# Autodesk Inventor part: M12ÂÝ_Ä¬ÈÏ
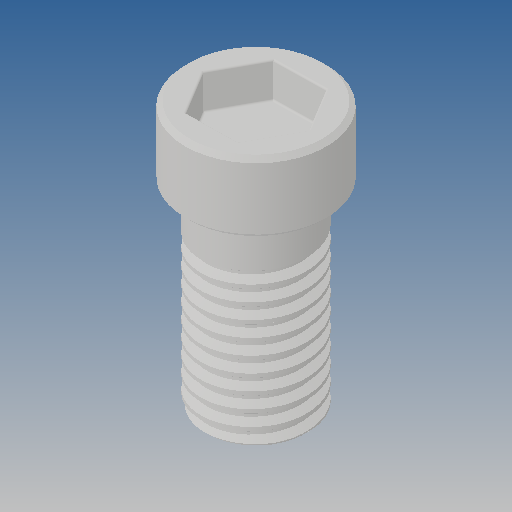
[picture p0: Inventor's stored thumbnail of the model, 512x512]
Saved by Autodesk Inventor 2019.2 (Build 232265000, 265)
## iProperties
Created: 2012-03
Part Number: M12ÂÝ_Ä¬ÈÏ
Material: Ogólny
Document SubType Name: Modeling
Designer: CADENGINEERING4
Density: 1 g/cm^3
Appearance: Domyślna
Author: CADENGINEERING4
Revision Number: ÈÎºÎ
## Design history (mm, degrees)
feature "NONE"
node "Bryła1"
